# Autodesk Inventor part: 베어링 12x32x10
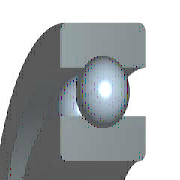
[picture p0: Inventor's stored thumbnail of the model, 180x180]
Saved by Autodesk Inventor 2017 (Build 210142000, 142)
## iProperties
IsCustomPart: 1
Created: 2012-02
Part Number: 베어링 12x32x10
Material: 강철, 연강
Description: 깊은 그루브 볼 베어링
Document SubType Name: Modeling
Standard: KS B 2023
Designer: test
Standards Organization: KS
Language: ko-KR
Size Designation: 6201 - 12 x 32 x 10
Categories: <MemberInstance><Categories><Category DisplayName="샤프트 부품" InternalName="7f7aeb1f-a693-4053-b835-cee3144e0d98" Mnemonic="SHFT"><Category DisplayName="베어링" Inter
Density: 1 g/cm^3
Appearance: 노란색
Author: test
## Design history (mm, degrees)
sketch "스케치" dims "d0" = 5.2 (= -0.26 x WD + 0.26 x BD)
  geometry: L1 (2.4, 11)-(7.6, 11); L2 (5, 11)-(5, 8.4); L3 (5, 11)-(5, 13.6); L4 (3.068, 9.26)-(0, 9.26); L5 (0, 6)-(10, 6); L6 (3.068, 12.74)-(0, 12.74); L7 (0, 16)-(10, 16); L8 (10, 6)-(10, 9.26); L9 (6.932, 9.26)-(10, 9.26); L10 (6.932, 12.74)-(10, 12.74); L11 (10, 16)-(10, 12.74); L12 (-1.4, 0)-(8.4, 0) reference; L13 (0, -0.3)-(0, 5.3) reference
  constraints: 22 end point, 4 point on line, 2 collinear, 2 perpendicular, 2 symmetric about line, 1 midpoint, 1 parallel, 14 other
  dimensions: "d9" = 12 diameter of L5 L12 (= WD); "d11" = 32 diameter of L7 L12 (= BD); "d12" = 10 distance between parallel lines of L8 L13 (= KB); "d13" = 18.52 diameter of L9 L12 (= 0.326 x BD + 0.674 x WD)
revolve "본체" stored, may be unused: angle "d6" = 90 deg
revolve "볼" stored, may be unused: angle "d7" = 90 deg
pattern_circular "IDS_ARRAYBALL[SIMPL:T]" dims angle "d3" = 360 deg
body "Solid1"
fillet "모깎기1" dims "d1" = 0.6 (= KRS)
other parameters: "WD" = 12 [user parameter; used in 5 equation terms], "BD" = 32 [user parameter; used in 5 equation terms], "KB" = 10 [user parameter; used in 1 equation term], "KRS" = 0.6 [user parameter; used in 1 equation term], "d4" = 0, "d5" = 0, "d8" = 0, "d14" = 0, "d15" = 0, "BBA" = 0 [user parameter], "BC0" = 3100000 [user parameter], "BC" = 6890000 [user parameter], "BR" = 16 (= 0.5 x BD) [user parameter], "WR" = 6 (= 0.5 x WD) [user parameter]
